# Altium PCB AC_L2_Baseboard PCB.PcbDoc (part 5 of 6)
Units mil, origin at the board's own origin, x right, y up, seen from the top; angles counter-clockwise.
Board outline 7290 x 7055 mil, 4 copper layers (Top Layer, Layer 1, Layer 2, Bottom Layer), stack 70.356 mil thick; 510 components, 285 nets, 1364 pads, 522 vias.
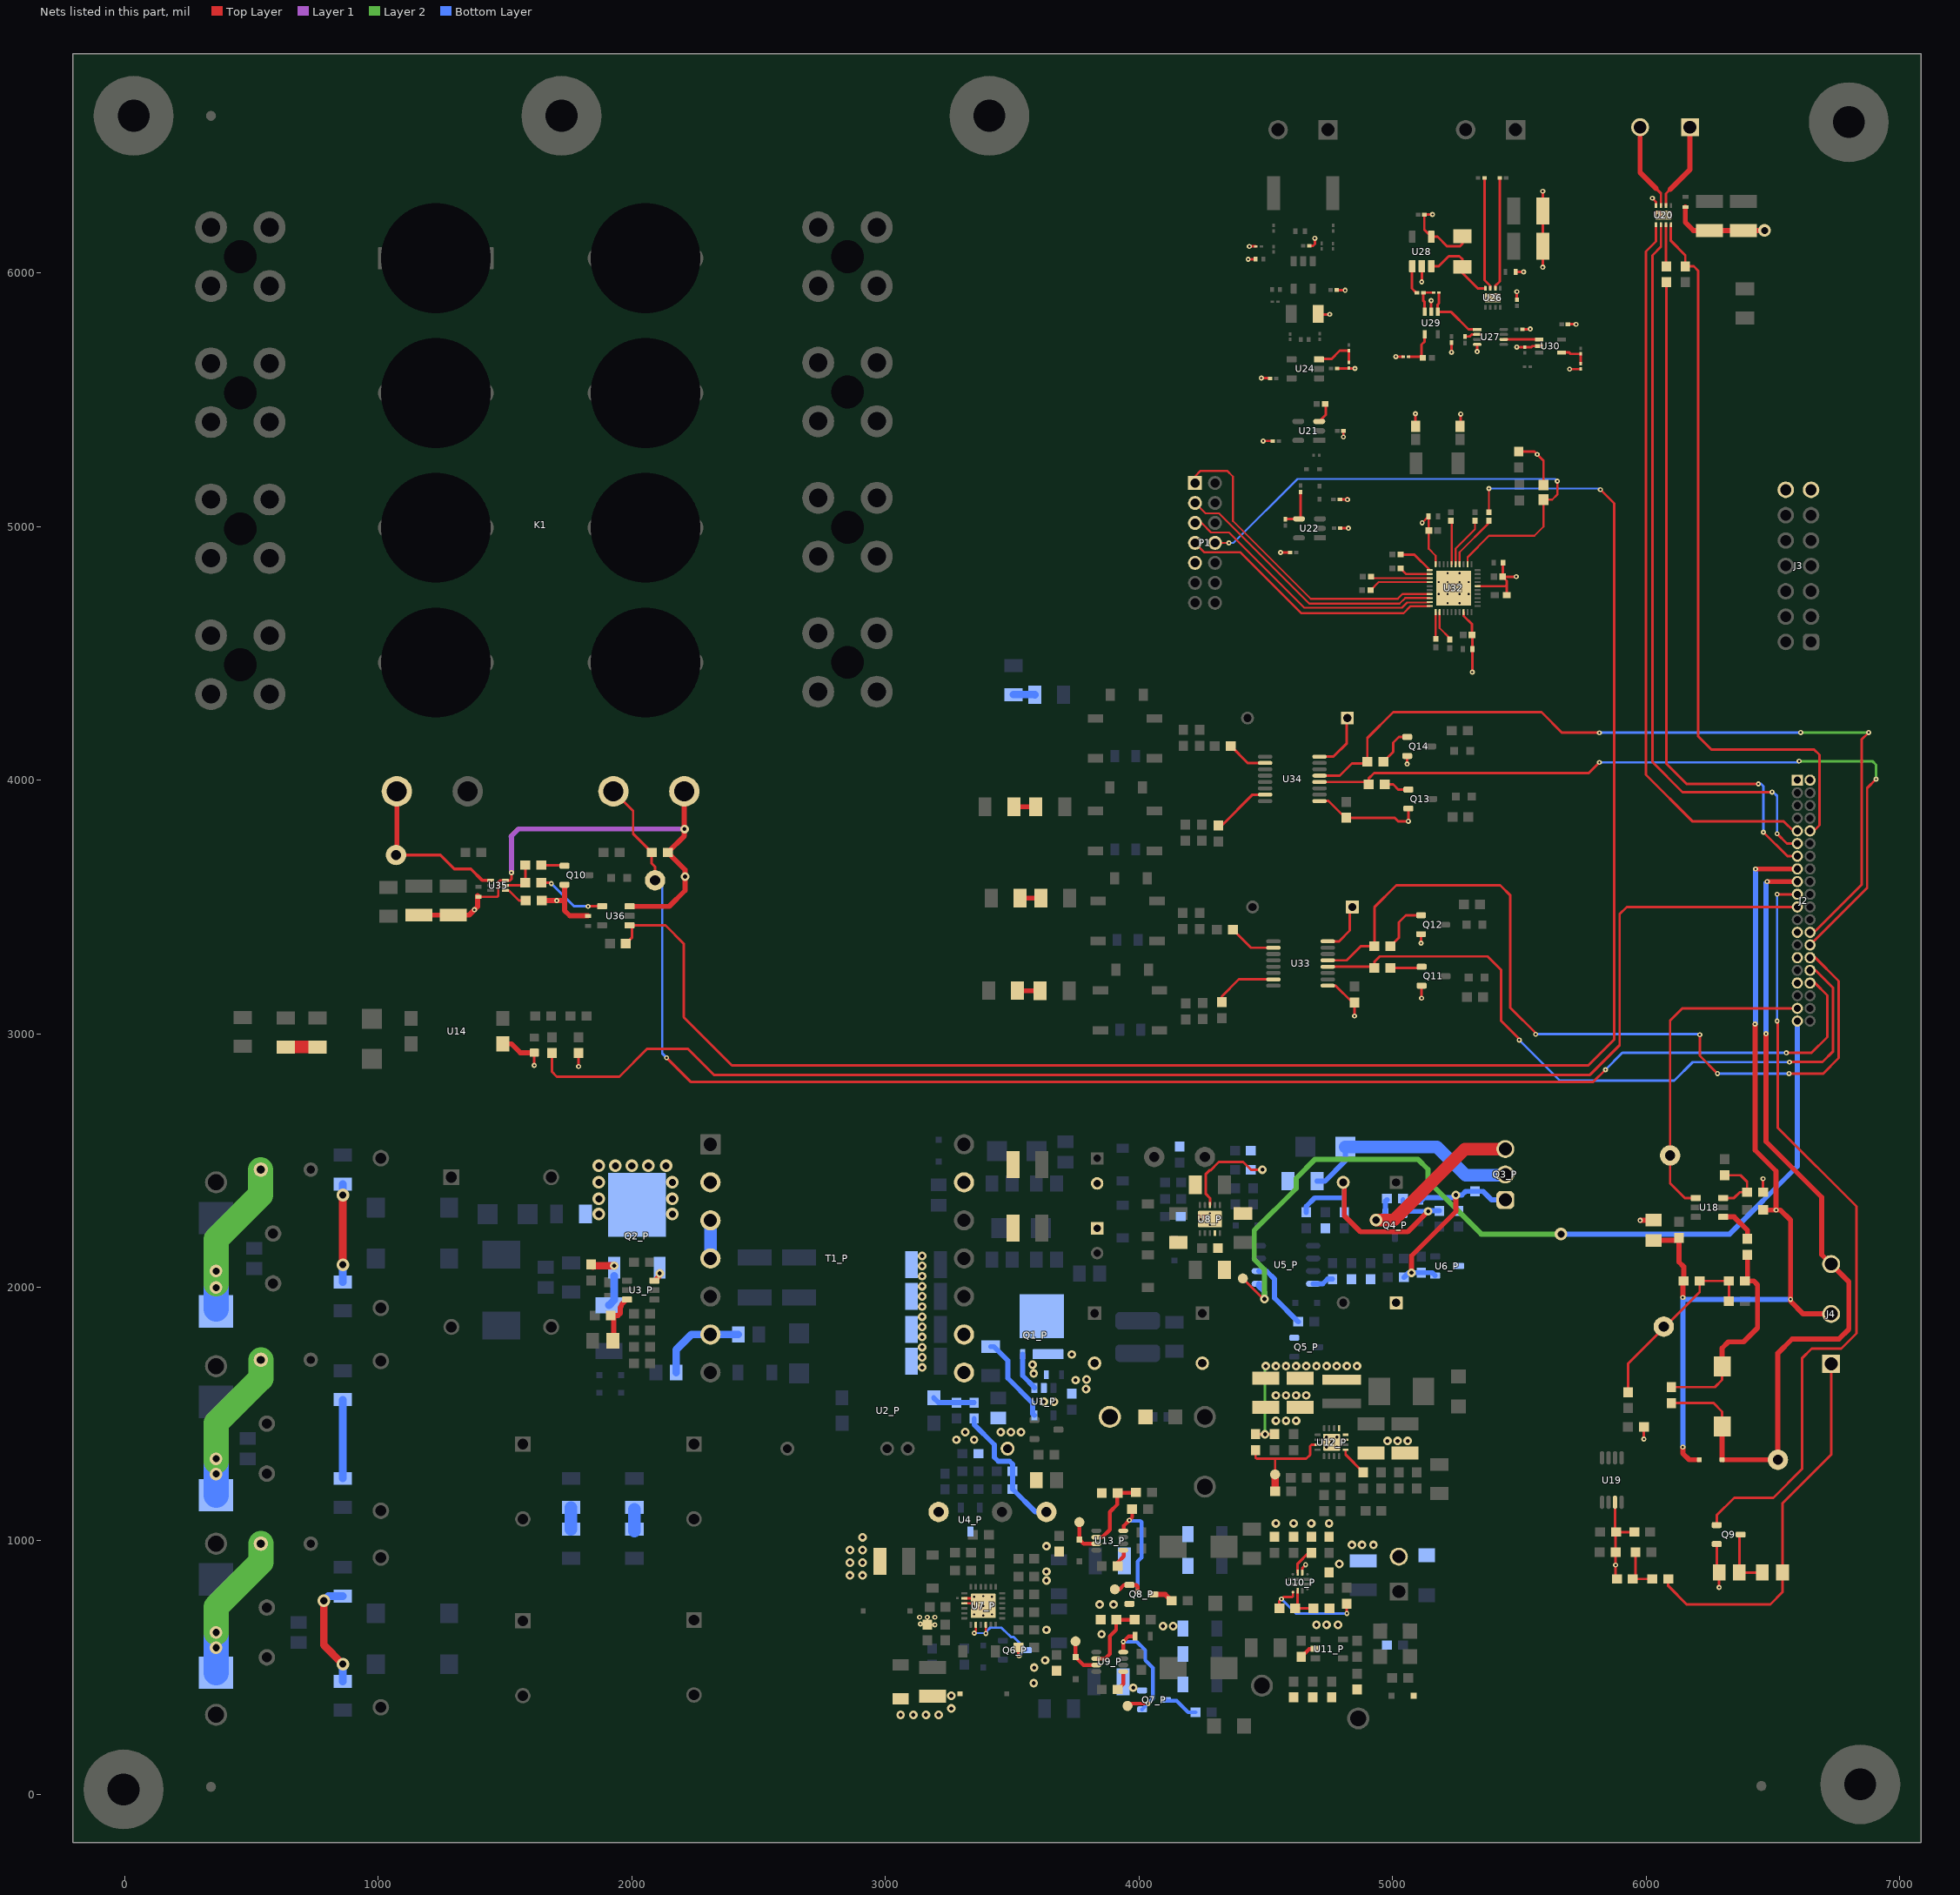
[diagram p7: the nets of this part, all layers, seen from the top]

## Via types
v1: diameter 34, hole 16, Top Layer to Bottom Layer, tented both sides, 231 vias
v2: diameter 20, hole 8, Top Layer to Bottom Layer, tented both sides, 209 vias
v3: diameter 50, hole 28, Top Layer to Bottom Layer, tented both sides, 48 vias
v4: diameter 19.68, hole 7.87, Top Layer to Bottom Layer, 29 vias
v5: diameter 24, hole 12, Top Layer to Bottom Layer, 5 vias

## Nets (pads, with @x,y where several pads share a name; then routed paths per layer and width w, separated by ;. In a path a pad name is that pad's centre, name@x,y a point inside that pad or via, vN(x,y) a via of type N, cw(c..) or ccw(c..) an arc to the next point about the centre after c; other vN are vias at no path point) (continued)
NetD200_P_2: D200_P.2 TP13_P.1 U9_P.7 | length 148.4
  Top Layer w15: TP13_P.1@3750,604 D200_P.2@3750,541.61 3781.35,510.26 U9_P.7@3823,510.26
NetD201_P_2: D201_P.2 TP17_P.1 U13_P.7 | length 142.2
  Top Layer w15: TP17_P.1@3765,1074 D201_P.2@3765,1005.61 3781.81,988.8 U13_P.7@3831.85,988.8
NetF1_P_1: F1_P.1 RT1_P.1 | length 674.1
  Layer 2 w30: RT1_P.1@535,2464 RT1_P.1@536.57,2464
  Layer 2 w100: v3@360,2014 360,2189 535,2364 RT1_P.1@535,2464
  Bottom Layer w100: F1_P.1@360,1914 v3(360,2064)
  other v3: 360,1999
NetF2_P_1: F2_P.1 RT2_P.1 | length 632.2
  Layer 2 w100: v3@360,1314 360,1464 536.57,1640.57 RT2_P.1@536.57,1714
  Bottom Layer w100: F2_P.1@360,1179.94 v3@360,1339
  other v3: 360,1264 360,1324
NetF3_P_1: F3_P.1 RT3_P.1 | length 582.2
  Layer 2 w100: v3(360,639) 360,739 536.57,915.57 RT3_P.1@536.57,989
  Bottom Layer w100: F3_P.1@360,479.94 v3(360,639)
  other v3: 360,579
NetL18_1: L18.1 R85.1 R87.2 R89.2 | length 824.7
  Top Layer w10: R85.1@6100,1606.5 6271.5,1606.5 6300,1635 L18.1@6300,1688.11
  Top Layer w20: L18.1@6300,1688.11 6300,1760 6325,1785 6385,1785 6440,1840 6440,2010 6425,2025 R89.2@6389.84,2025 ; R89.2@6400,2040.16 R87.2@6400,2128.5
NetQ1_P_4: Q1_P.4 U1_P.1 | length 152.5
  Bottom Layer w20: Q1_P.4@3541.54,1736.2 3541.54,1651.56 3588.07,1605.03 3587.6,1604.55 U1_P.1@3587.6,1603.13
NetQ1_P_5-6-7-8: Q1_P.5-6-7-8 R22_P.2 T1_P.8 T1_P.9 U1_P.5 | length 350.5
  Bottom Layer w20: R22_P.2@3415,1766.09 3427.91,1766.09 3482.72,1711.28 3482.72,1641.28 3580.2,1543.8 3580.2,1501.85 3587.18,1494.87 U1_P.5@3587.6,1494.87
NetQ2_P_1: Q2_P.1 U3_P.3 | length 38
  Top Layer w20: U3_P.3@2089.13,2026.4 2090.35,2026.4 2110,2046.05 v1(2110,2055)
NetQ2_P_3: Q2_P.3 R33_P.2 R35_P.2 | length 217.2
  Top Layer w30: R33_P.2@1840,2090.5 1846.5,2084 1847.5,2085 v1(1930,2085)
  Bottom Layer w30: R35_P.2@1910,1929.55 1930,1949.55 Q2_P.3@1930,2045.38
NetQ2_P_4: Q2_P.4 R11_P.1 T1_P.2
  other v3: 1870,2289 2160,2289 1870,2349 2160,2349 1870,2414 2160,2414 1870,2479 1935,2479 2000,2479 2065,2479 2135,2479
NetQ6_P_3: Q6_P.3 R53_P.1 U7_P.8 U7_P.10 | length 424.2
  Top Layer w8: v2(3350.25,636) 3350.25,639.25 3356.25,645.25 3356.25,668.98 U7_P.8@3356.47,669.2 ; U7_P.10@3395.84,669.2 3395.84,635.16 v2(3396,635)
  Top Layer w10: R53_P.1@3511,565.5 R53_P.1@3524.5,579 3524.5,548.5 v2(3527,546)
  Bottom Layer w8: v2(3350.25,636) 3395,636 v2(3396,635)
  Bottom Layer w10: v2(3396,635) 3400.13,635 3400.13,644.47 3413.53,657.87 3457.56,657.87 3484.35,631.09 3485.31,631.09 3495.46,620.94 3506.3,620.94 Q6_P.3@3558.24,569 3550,569 v2(3527,546)
NetQ7_P_1: Q7_P.1 R61_P.1 TP15_P.1 U9_P.4 | length 543.2
  Top Layer w15: U9_P.4@3938.15,561.44 v2(3938.15,602.15) 3960,624 R61_P.1@3983.5,624 ; TP15_P.1@3955,349 3964.29,358.29 v2(4035.39,358.29)
  Bottom Layer w15: v2(3938.15,602.15) 3991.85,602.15 4025,569 4025,529 4055,499 4055,377.9 v2(4035.39,358.29) Q7_P.1@4012.76,335.65
NetQ7_P_3: Q7_P.3 R64_P.1 | length 138.5
  Bottom Layer w15: Q7_P.3@4107.24,373.06 4107.24,369.74 4107.64,369.35 4148.63,369.35 4193.98,324 R64_P.1@4223.5,324
NetQ8_P_1: Q8_P.1 R74_P.1 TP20_P.1 U13_P.4 | length 553.6
  Top Layer w15: TP20_P.1@3905,809 3924,809 3941.4,826.4 Q8_P.1@3962.76,826.4 3989.95,826.4 3995,821.35 v2(3995,799) ; U13_P.4@3938.15,1039.98 3940.51,1042.35 3940.51,1059.96 v2(3962.01,1081.46) 3973.5,1092.96 R74_P.1@3973.5,1125
  Bottom Layer w15: v2(3962.01,1081.46) 3964.47,1079 4005,1079 4010,1074 4010,934 3995,919 v2(3995,799)
NetQ8_P_3: Q8_P.3 R79_P.1 | length 81.6
  Top Layer w20: Q8_P.3@4057.24,789 4103.5,789 R79_P.1@4128.5,764
NetQ9_3: Q9.3 R93.1 R97.2 | length 242.1
  Top Layer w10: Q9.3@6373.29,1025 6368.29,1020 R97.2@6368.29,875 R93.1@6458.29,875
NetQ10_1: Q10.1 R216.2 | length 92.3
  Top Layer w10: R216.2@1642.97,3665.04 1731.63,3665.04 Q10.1@1734.23,3662.44
NetQ11_1: Q11.1 R219.2 | length 125.2
  Top Layer w10: R219.2@4991.5,3260 5110.65,3260 Q11.1@5114.92,3264.27
NetQ12_1: Q12.1 R220.2 | length 208
  Top Layer w10: R220.2@4991.5,3345 5025,3378.5 5025,3440 5052.4,3467.4 Q12.1@5112.76,3467.4
NetQ13_1: Q13.1 R221.2 | length 101.8
  Top Layer w10: R221.2@4968.94,3983.01 5002.44,3983.01 5022.44,3963.01 Q13.1@5062.44,3963.01
NetQ14_1: Q14.1 R222.2 | length 155.7
  Top Layer w10: R222.2@4963.94,4073.01 5002.44,4111.52 5002.44,4148.01 5024.84,4170.41 Q14.1@5057.95,4170.41
NetR2_P_1: R2_P.1 R7_P.2 | length 385.8
  Top Layer w30: v3(860,2089) v3(860,2364)
  Bottom Layer w30: R7_P.2@860,2021.09 v3(860,2089) ; v3(860,2364) R2_P.1@860,2406.91
NetR5_P_1: R5_P.1 R8_P.2 | length 85.8
  Bottom Layer w50: R8_P.2@1760,1046.09 R5_P.1@1760,1131.91
NetR9_P_1: R9_P.1 R12_P.2 | length 310.8
  Bottom Layer w30: R12_P.2@860,1246.09 R9_P.1@860,1556.91
NetR13_P_1: R13_P.1 R17_P.2 | length 85.8
  Bottom Layer w50: R13_P.1@2010,1039 R17_P.2@2010,1124.83
NetR16_P_1: R16_P.1 R19_P.2 | length 431.4
  Top Layer w30: v3(785,764) 785,589 v3(860,514)
  Bottom Layer w30: v3(785,764) 802.91,781.91 R16_P.1@860,781.91 ; R19_P.2@860,446.09 v3(860,514)
NetR21_P_1: R21_P.1 R25_P.2 R27_P.2 TP8_P.1 | length 538.4
  Bottom Layer w20: R25_P.2@3350,1482.5 3350,1459 3430,1379 3430,1329 3445,1314 3490,1314 3501.5,1302.5 R27_P.2@3501.5,1274 R21_P.1@3501.5,1204 3591.5,1114 TP8_P.1@3635,1114
NetR23_P_2: R23_P.2 R26_P.2 T1_P.6 | length 359.9
  Bottom Layer w30: R26_P.2@2175,1664 2175,1754 2235,1814 T1_P.6@2310,1814 R23_P.2@2420,1814
NetR24_P_1: R24_P.1 R25_P.1 U2_P.1 | length 167.1
  Bottom Layer w20: U2_P.1@3190.61,1564 3209.11,1545.5 R24_P.1@3280,1545.5 R25_P.1@3350,1545.5
NetR28_P_1: R28_P.1 R31_P.2 U3_P.6 | length 216.5
  Top Layer w20: R28_P.1@1925,1789 1928.31,1789 1928.31,1877.19 R31_P.2@1916.5,1889 1946.02,1889 1953.82,1896.8 1953.82,1920.51 1958.7,1925.39 1958.7,1931.75 1979.02,1952.07 1979.5,1951.6 U3_P.6@1980.87,1951.6
NetR29_1: R29.1 R83.2 | length 125
  Top Layer w50: R29.1@635,2947.91 R83.2@760,2947.91
NetR36_P_2: R36_P.2 U5_P.6 | length 282.4
  Bottom Layer w20: U5_P.6@4472.72,2064 4503.31,2064 4535,2032.31 4535,1957.5 R36_P.2@4628.5,1864
NetR55_P_1: R55_P.1 U8_P.8 | length 429.9
  Top Layer w10: U8_P.8@4280,2324.12 4280,2352 4264,2368 4264,2447 4278.13,2461.13 4281.9,2461.13 4314.78,2494 4411.5,2494 4441.5,2464 v1(4487,2464)
  Bottom Layer w10: R55_P.1@4441.5,2464 v1(4487,2464)
NetR60_P_1: R60_P.1 R63_P.2 U10_P.1 | length 426.8
  Top Layer w10: R63_P.2@4553.5,734 4553.5,762.5 v2(4561.75,770.75) 4570,779 4605,779 4607.44,781.44 U10_P.1@4607.44,797.66 ; v2(4820,714) R60_P.1@4820,752.5
  Bottom Layer w10: v2(4561.75,770.75) 4618.5,714 v2(4820,714)
NetR62_P_1: R62_P.1 R65_P.2 U9_P.6 | length 278.7
  Top Layer w15: U9_P.6@3831.85,535.85 3866.85,535.85 3885,554 3885,624 3910,649 3910,687.5 R65_P.2@3911.5,689 R62_P.1@3983.5,689
NetR63_P_1: R63_P.1 R67_P.2 U10_P.2 | length 145.6
  Top Layer w10: U10_P.2@4626.14,803.57 4625.63,803.06 4625.63,790.13 4625.31,789.81 4625.31,742.82 R63_P.1@4616.5,734 R67_P.2@4688.5,734
NetR66_P_2: R66_P.2 U10_P.9 | length 107.1
  Top Layer w10: U10_P.9@4626.14,874.43 4626.14,910.14 4668.5,952.5 R66_P.2@4680,952.5
NetR70_P_1: R70_P.1 R201_P.2 TP18_P.1 U12_P.3 | length 449.2
  Top Layer w10: R70_P.1@4460,1357.5 4460,1327.98 4463.98,1324 4535,1324 ; TP18_P.1@4537.01,1262.01 4537.01,1321.99 4535,1324 ; U12_P.3@4704.88,1379.16 4680.16,1379.16 4675,1374 4675,1339 4660,1324 4535,1324
  Top Layer w30: R201_P.2@4537.01,1195 TP18_P.1@4537.01,1262.01
NetR76_P_1: R76_P.1 R80_P.2 U13_P.6 | length 296.5
  Top Layer w15: U13_P.6@3831.85,1014.39 3855.39,1014.39 3885,1044 3885,1114 3915,1144 3915,1187.5 R80_P.2@3916.5,1189 3986.1,1189 R76_P.1@3988.5,1191.4
NetR78_P_2: R78_P.2 U12_P.9 | length 117.9
  Top Layer w10: U12_P.9@4815.12,1359.47 4815.12,1340.38 R78_P.2@4885,1270.5
NetR86_1: R86.1 R88.2 U18.3 | length 244.3
  Top Layer w10: U18.3@6304.13,2352.4 6347.4,2352.4 6370,2375 R88.2@6398.5,2375 6398.5,2416.5 6372.99,2442.01 R86.1@6310,2442.01
NetR87_1: R87.1 U18.1 | length 151.2
  Top Layer w20: U18.1@6304.13,2277.6 6347.4,2277.6 6400,2225 R87.1@6400,2191.5
NetR94_1: R94.1 R95.1 R96.2 | length 186.4
  Top Layer w10: R95.1@5958.5,955 5958.5,860.71 R96.2@5947.8,850 R94.1@6024.8,850
NetR99_2: R99.2 U32.34 | length 219.3
  Top Layer w8: U32.34@5264.65,4851.89 5264.65,4899.06 5380.56,5014.96 R99.2@5380.56,5023.23
NetR125_1: R125.1 U20.7 | length 165.1
  Top Layer w10: U20.7@6078.5,6190.94 6078.5,6027.99 R125.1@6080,6026.5
NetR137_2: R137.2 R138.1 U22.4 | length 164
  Top Layer w10: R138.1@4576.62,5030.77 R138.1@4578.04,5029.35 4578.55,5029.87 4630.69,5029.87 U22.4@4631.2,5030.38 4637.56,5036.74 R137.2@4637.56,5136.17
NetR144_2: R144.2 U21.3 | length 83.3
  Top Layer w10: U21.3@4710.95,5414.8 4736.46,5440.32 R144.2@4736.46,5487.56
NetR151_1: R151.1 U26.2 | length 442.3
  Top Layer w10: U26.2@5405.56,5939.76 5405.56,5949.25 5422.76,5966.45 R151.1@5422.76,6374.96
NetR152_1: R152.1 U26.3 | length 444.5
  Top Layer w10: R152.1@5363.35,6374.96 5363.35,5971.77 5385.87,5949.25 U26.3@5385.87,5939.76
NetR154_2: R154.2 U27.2 | length 51.1
  Top Layer w10: R154.2@5286.56,5749.76 5303.76,5749.76 5311.48,5757.48 5334.03,5757.48 U27.2@5334.36,5757.8
NetR155_1: R155.1 U28.1 | length 115.1
  Top Layer w10: U28.1@5078.16,6026.89 5076.86,6025.59 5076.86,5939.09 5094.39,5921.56 R155.1@5096.35,5921.56
NetR155_2: R155.2 R156.1 U29.3 | length 114.8
  Top Layer w10: R155.2@5121.95,5921.56 5121.95,5890.34 5126.97,5885.32 U29.3@5126.97,5847.14 ; R155.2@5124.45,5922.96 R156.1@5161.73,5922.96 R156.1@5162.73,5922.96
NetR156_2: R156.2 U27.1 U29.1 | length 263
  Top Layer w10: R156.2@5183.38,5922.96 5183.38,5880.38 5178.15,5875.15 U29.1@5178.15,5847.14 5230.05,5847.14 5299.7,5777.49 U27.1@5334.36,5777.49
NetR175_2: R175.2 U32.1 | length 139.1
  Top Layer w10: R175.2@5032.41,4889.72 5086.15,4889.72 U32.1@5146.54,4829.33
NetR178_2: R178.2 U32.2 | length 123.3
  Top Layer w8: R178.2@5032.41,4834.72 5054.61,4812.52 U32.2@5146.54,4812.52
NetR179_2: R179.2 U32.3 | length 236.6
  Top Layer w8: R179.2@4911.73,4801 4915.96,4796.77 U32.3@5146.54,4796.77
NetR180_2: R180.2 U32.4 | length 246.1
  Top Layer w8: R180.2@4913.73,4749 4945.76,4781.02 U32.4@5146.54,4781.02
NetR184_2: R184.2 U32.11 | length 105.9
  Top Layer w8: U32.11@5170.16,4662.91 5170.16,4558.27 R184.2@5171.03,4557.4
NetR187_2: R187.2 U32.12 | length 125.4
  Top Layer w8: U32.12@5185.91,4662.91 5185.91,4600.31 5226.03,4560.2 R187.2@5226.03,4554.13
NetR189_2: R189.2 U32.35 | length 203.1
  Top Layer w8: U32.35@5248.9,4851.89 5248.9,4913.31 5325.56,4989.96 R189.2@5325.56,5023.23
NetR190_2: R190.2 U32.36 | length 172.4
  Top Layer w8: R190.2@5230.56,5023.23 5233.16,5020.63 U32.36@5233.16,4851.89
NetR192_2: R192.2 R193.1 | length 89
  Top Layer w20: R193.1@3521.34,3170 3521.77,3169.57 R192.2@3610.16,3169.57
NetR194_1: R194.1 U33.15 | length 254.1
  Top Layer w10: R194.1@4326.73,3124.19 4326.73,3146.73 4394.37,3214.37 U33.15@4530.28,3214.37
NetR195_2: R195.2 R196.1 | length 82
  Top Layer w20: R196.1@3532.01,3534.57 R196.1@3531.57,3535 R195.2@3612.91,3535
NetR198_1: R198.1 U33.10 | length 188.6
  Top Layer w10: R198.1@4370.94,3410 4441.57,3339.37 U33.10@4530.28,3339.37
NetR200_2: R200.2 R201.1 | length 85.9
  Top Layer w20: R201.1@3507.01,3895.31 R200.2@3592.91,3895.31
NetR202_1: R202.1 U34.15 | length 234.4
  Top Layer w10: R202.1@4313.54,3821.5 4326.5,3821.5 4447.81,3942.81 U34.15@4497.72,3942.81
NetR203_2: R203.2 R204.1 | length 84.1
  Bottom Layer w30: R204.1@3505,4337.48 3588.43,4337.48 R203.2@3588.91,4337
NetR206_1: R206.1 U35.1 | length 96.6
  Top Layer w10: U35.1@1501.47,3565.04 1514.96,3565.04 1554.96,3525.04 R206.1@1581.47,3525.04
NetR207_1: R207.1 U34.10 | length 163.6
  Top Layer w10: R207.1@4361.93,4135 4429.11,4067.81 4442.64,4067.81 U34.10@4497.72,4067.81
NetR209_1: R209.1 U36.4 | length 279.1
  Top Layer w10: R209.1@1642.97,3595.04 v2@1684.96,3595.04 ; v2(1827.56,3502.44) U36.4@1882.34,3502.44
  Bottom Layer w10: v2(1682.56,3592.44) 1772.56,3502.44 v2(1827.56,3502.44)
NetT1_P_3: T1_P.3 T1_P.4 | length 150
  Bottom Layer w50: T1_P.4@2310,2114 T1_P.3@2310,2264
NetU27_6: U27.6 U30.1 | length 140.7
  Top Layer w10: U27.6@5438.76,5738.12 5439.04,5737.83 5577.65,5737.83 5577.82,5738 U30.1@5578.27,5737.55 U30.1@5577.72,5737
OUT1: J15.1 U20.2 | length 348.6
  Top Layer w10: U20.2@6078.5,6265.75 6078.5,6313.5 6095,6330
  Top Layer w20: 6095,6330 6173.43,6408.43 J15.1@6173.43,6575
OUT2: J15.2 U20.3 | length 343.3
  Top Layer w10: 6040,6333 6058.82,6314.18 U20.3@6058.82,6265.75
  Top Layer w20: J15.2@5976.57,6575 5976.57,6396.43 6040,6333
PE_CP: C99.2 C100.2 D35.2 J2.15 J4.2 NT3.2 R91.1 | length 3637.8
  Top Layer w10: C99.2@6120,2185 C99.2@6130,2195 ; R91.1@6145,2021.5 R91.1@6148.5,2025 ; v2@6570,1945 v2(6570,1952.5)
  Top Layer w20: NT3.2@6030,2185 C99.2@6120,2185 ; C99.2@6130,2195 6130,2100 6148.5,2081.5 R91.1@6148.5,2025 ; v2(6145,1370) 6145,1345 6170,1320 D35.2@6210.12,1320 ; v2(6145,1960) R91.1@6145,2021.5 ; v2(6430,3038) 6430,2541 6513,2458 v2(6513,2305) ; v2(6432,3650) J2.15@6597,3650 ; C100.2@6461.5,2305 v2(6513,2305) ; v2@6570,1945 6620,1895 J4.2@6730,1895 ; v2(6570,1952.5) 6570,2265 6530,2305 v2(6513,2305)
  Bottom Layer w10: v2(6145,1960) 6152.5,1952.5 ; v2(6430,3038) v2@6432,3040
  Bottom Layer w20: v2(6145,1370) v2(6145,1960) ; 6152.5,1952.5 v2(6570,1952.5) ; v2@6432,3040 v2(6432,3650)
PGND: C3_P.1 C4_P.2 C5_P.2 C10_P.1 C12_P.1 C18_P.2 C19_P.2 C21_P.2 C22_P.2 C23_P.2 C24_P.2 C25_P.2 C26_P.2 C27_P.2 C31_P.2 C33_P.2 C39_P.1 C40_P.2 C41_P.2 C42_P.2 C43_P.2 C44_P.2 C47_P.2 C48_P.2 C50_P.2 C51_P.2 C53_P.2 C54_P.2 C59_P.2 C60_P.1 C61_P.2 C64_P.2 C65_P.2 C66_P.2 C67_P.2 C68_P.2 C69_P.2 C70_P.2 C71_P.1 C72_P.2 C73_P.2 C74_P.2 C75_P.1 C76_P.2 C77_P.2 C79_P.2 C80_P.2 C81_P.2 C83_P.2 C84_P.2 C87_P.2 C88_P.2 C89_P.2 C90_P.2 C94_P.1 C96.2 C98.1 C108.2 C109.2 C110.2 C111.2 C114.2 C115.2 C116.2 C117.1 C118.1 C119.1 C120.1 C121.1 C122.1 C123.1 C124.1 C125.1 C126.1 C127.1 C128.1 C133.2 C134.2 C138.2 C139.2 C140.2 C141.2 C146.2 C147.1 C148.1 C149.2 C150.1 C151.2 C152.2 C153.1 C154.2 C155.1 C157.2 C159.1 C160.2 C161.2 C162.2 C164.2 C166.1 C167.2 C800.1 D11_P.1 D26_P.2 D28_P.1 J1_P.2 J2.1 J2.2 J2.25 J2.29 J2.33 J3.13 J3.14 K1.8 L10_P.2 NT1_P.1 NT2_P.2 NT3.1 P1.9 Q1_P.1-2-3 Q5_P.2 Q7_P.2 Q8_P.2 Q9.2 Q10.2 Q11.2 Q12.2 Q13.2 Q14.2 R32_P.1 R44_P.1 R45_P.1 R49_P.1 R65_P.1 R66_P.1 R67_P.1 R68_P.1 R80_P.1 R88.1 R96.1 R97.1 R131.1 R133.1 R134.1 R147.1 R148.2 R153.1 R188.1 R202_P.1 R206.2 R218.2 T1_P.13 TP7_P.1 TP9_P.1 U1_P.2 U4_P.3 U5_P.4 U6_P.3 U7_P.2 U7_P.3 U7_P.25@3386,744 U8_P.4 U8_P.11 U9_P.1 U10_P.8 U11_P.2 U12_P.11 U12_P.12 U12_P.13 U12_P.17@4760,1389 U13_P.1 U14.3 U19.3 U20.4 U20.9 U26.9 U27.4 U28.2 U28.4 U29.2 U30.2 U32.18 U32.26 U32.40 U32.41 U33.1 U33.8 U34.1 U34.8 U35.3 U36.3 | length 7916.2
  Top Layer w8: v2(4490,5337.4) C123.1@4527.61,5337.4 ; C166.1@4820,4243.15 C166.1@4821.85,4245 ; v2(5116.86,5014.96) C154.2@5141.86,5039.96 5143.23,5038.58 C155.1@5143.23,4984.96 5143.23,4912.28 5170.16,4885.35 U32.40@5170.16,4851.89 ; U32.26@5335.52,4765.28 5445.2,4765.28 5451.03,4771.1
  Top Layer w10: C162.2@1395,3540 1469,3540 1473,3544 1473,3598 1479.41,3604.41 U35.3@1501.47,3604.41 1519.41,3604.41 1525,3610 v2(1525,3635) ; v2(1615,2875) C98.1@1615,2925.47 ; v2(1790,2871) C96.2@1790,2923.5 ; U7_P.3@3311.2,753.84 3337.77,753.84 v4(3347.61,744) ; U7_P.2@3311.2,773.53 3354.47,773.53 3350,778 v4(3350,780) ; v2(4430.56,6053.96) 4431.1,6054.5 4458.9,6054.5 C134.2@4459.44,6055.04 ; v2(4435.56,6104.96) R148.2@4460.91,6105 ; v2(4482.56,5585.96) 4483.34,5585.18 4516.83,5585.18 C122.1@4517.61,5584.4 ; v2(4558.56,4897.96) C124.1@4596.73,4897.96 ; 4644.02,887.12 4644.02,893.02 v2(4657,906) ; C117.1@4671.79,6106.96 4686.63,6106.96 4694,6114.33 v2@4694,6136.52 ; C133.2@4706.41,5826.07 C133.2@4706.41,5838.79 4708.24,5836.96 v2(4752.56,5836.96) ; U34.1@4712.28,3917.81 4747.64,3917.81 4813.94,3851.52 C164.2@4817.44,3851.52 5008.94,3851.52 5022.44,3838.01 v2(5062.44,3838.01) Q13.2@5062.44,3888.21 ; U34.8@4712.28,4092.81 4767.24,4092.81 4820,4145.57 C166.1@4820,4243.15 ; U33.1@4744.84,3189.37 4775.63,3189.37 4841.5,3123.5 C157.2@4850,3123.5 ; U33.8@4744.84,3364.37 4789.37,3364.37 4831.85,3406.85 4831.85,3490 C159.1@4841.85,3500 ; C121.1@4780.17,5933.04 4780,5933.04 4780.54,5932.5 4813.02,5932.5 v2(4813.56,5931.96) ; C118.1@4781.55,5623.4 v2@4854.6,5623.4 ; R147.1@4792.56,5106.96 v2@4821.95,5106.96 ; C120.1@4793.78,4993.57 v2(4826.34,4993.57) ; v2(4806.57,5353.43) C119.1@4806.57,5377.4 ; R131.1@4826.53,5624.07 R131.1@4827.59,5625.13 ; v2(4850,3070) 4850,3103.5 ; v2(5013.26,5670.26) R133.1@5041.73,5670.26 ; v2(5057.95,4063.52) Q14.2@5057.95,4095.61 ; v2(5090.14,5444.99) 5090.14,5395.59 C147.1@5090.56,5395.18 ; v2(5112.76,3357.24) Q12.2@5112.76,3392.6 ; v2@5114.92,3135.08 v2(5114.92,3140) Q11.2@5114.92,3189.47 ; v2(5115.56,5964.96) U28.2@5115.56,6026.89 ; U29.2@5152.56,5847.14 v2(5152.56,5890.96) ; v2(5157.89,6230.66) 5157.54,6230.31 5125.9,6230.31 C127.1@5125.56,6229.96 5125.56,6170.43 U28.4@5152.96,6143.03 5177.49,6143.03 5215.56,6104.96 5265.56,6104.96 5275.56,6114.96 R153.1@5275.56,6145.04 ; v2@5232.96,5682.44 C125.1@5232.96,5725.46 ; C148.1@5265.56,5395.18 5269.14,5398.77 v2(5269.14,5443.99) ; U32.18@5280.4,4662.91 5281.21,4662.1 5281.21,4647.7 5313.35,4615.56 C150.1@5313.35,4572.4 5314.73,4571.02 C149.2@5314.73,4517.4 v2(5314.73,4425.79) ; v2@5334.36,5690.16 U27.4@5334.36,5718.43 ; C152.2@5436.11,4857.4 5434.73,4856.02 C153.1@5434.73,4802.4 ; C146.2@5451.03,4729.72 5451.03,4771.1 5451.03,4786.1 C153.1@5434.73,4802.4 ; v2(5488,4802.4) C153.1@5434.73,4802.4 ; C140.2@5489.57,6004.34 v2@5519.57,6004.34 ; v2(5490.43,5707.96) C141.2@5521.54,5707.97 ; v2(5490.56,5926.59) 5490.8,5926.36 5490.8,5894.78 C126.1@5491.04,5894.54 ; C151.2@5497.82,5295.91 5559.61,5295.91 v2(5570.56,5284.96) 5595.56,5259.96 R188.1@5595.56,5163.53 ; C800.1@5511.98,5778 5511.81,5778 5512.4,5778.59 5542.71,5778.59 v2(5543.3,5779.17) ; C141.2@5521.56,5707.98 5547.71,5707.98 5551.69,5711.96 U30.2@5578.27,5711.96 ; v2@5592.64,6032.05 C138.2@5592.64,6104.96 C139.2@5592.64,6244.96 v2(5592.64,6322.87) ; C128.1@5691.54,5797.96 v2(5723.96,5797.96) ; v2(5698.38,5621.13) R134.1@5742.56,5621.13 ; U19.3@5877.8,1152.4 5877.8,1035.71 C109.2@5878.5,1035 ; R96.1@5884.8,850 5880,854.8 C108.2@5880,955 5880,1033.5 C109.2@5878.5,1035 ; C111.2@5953.5,1035 C109.2@5881.5,1035 C109.2@5878.5,1035 ; v2(5991.5,1401.5) C110.2@5991.5,1450 ; v2(6025,6295) 6039.13,6280.87 U20.4@6039.13,6265.75 ; NT3.1@6029,2264 NT3.1@6030,2265 ; Q9.2@6278.8,987.6 6278.8,884.49 R97.1@6288.29,875 v2(6288.29,816.71) ; v2@6460,2430 v2(6461.5,2428.5) R88.1@6461.5,2375
  Top Layer w15: C65_P.2@3916.5,414 3938.15,435.65 U9_P.1@3938.15,484.67 ; C88_P.2@3916.5,900.61 3916.5,915.5 3940,939 3940,961.36 U13_P.1@3938.15,963.21 ; C81_P.2@4640,542.5 4671.5,574 U11_P.2@4698.82,574
  Top Layer w20: C160.2@1160,3467.91 C161.2@1295,3467.91 1357.99,3467.91 v2(1379,3488.92) 1391.47,3501.4 C162.2@1391.47,3545.04 ; U14.3@1490.61,2960 1525,2960 1559.53,2925.47 C98.1@1615,2925.47 ; R206.2@1644.47,3525.04 1729.19,3525.04 1734.23,3520 ; Q10.2@1734.23,3587.64 1734.23,3520 ; C167.2@1826.47,3465.04 1754.96,3465.04 1734.23,3485.77 1734.23,3520 ; U36.3@1990.61,3502.44 2147.44,3502.44 2210,3565 v1(2210,3620) 2210,3646.51 R218.2@2141.47,3715.04 2206.93,3780.49 K1.8@2206.93,3955.94 ; v2@4821.95,5106.96 v2(4822.34,5106.57) ; v2(5977,2264) NT3.1@6029,2264 ; C116.2@6155,6260 6155,6200 6187.2,6167.8 C115.2@6249.76,6167.8 C114.2@6384.33,6167.8 v3(6467.8,6167.8)
  Layer 1 w20: v2@1525,3634.92 v2(1525,3635) 1525,3775.12 1522.56,3777.56 1552.44,3807.44 v1(2207.56,3807.44)
  Bottom Layer w20: U5_P.4@4687.28,2014 4725,2014 4743.5,2032.5 C42_P.2@4763.7,2032.5
  other v1: 3060,314 3110,314 3160,314 3210,314 3260,339 3260,389 3977.52,421.01 3585,439 3586.79,500.1 3630,529 3852.65,632.15 3635,649 4095,664 4135,664 4700,669 4740,669 4785,669 3845,749 3900,749 3635,844 2860,864 2910,864 3635,879 4790,909 2860,914 2910,914 2860,964 2910,964 3635,979 4840,984 4880,984 4925,984 2910,1014 4540,1069 4610,1069 4680,1069 4750,1069 4980,1394 5020,1394 5060,1394 3280,1399 3350,1399 3315,1429 3455,1429 3495,1429 3535,1429 4540,1474 4580,1474 4620,1474 3625,1549 3665,1549 4540,1574 4580,1574 4620,1574 4660,1574 3791.02,1599 3750,1634 3793.43,1636.53 3585,1660 3145,1684 3580,1695 3145,1724 3735,1735 3145,1764 3145,1804 3145,1844 3145,1884 3145,1924 3145,1964 3145,2004 3145,2044 3145,2084 3145,2124
  other v2: 3195,669 3138.25,672.25 3135,699 3165,699 3195,699 5880,904.9 1704,3525.04 4851.86,5623.4 5232.96,5687.44 5334.24,5690.02 5517.13,6004.34 5592.64,6022.87 4693.56,6136.96
  other v4: 3386,705.61 3350,710 3420,710 3386,744 3424.39,744 3420,780 3386,782.39 4280,2246.36 4242.6,2269 4317.4,2269 4280,2291.64 5217.41,4698.35 5264.65,4698.35 5181.97,4733.78 5217.41,4733.78 5264.65,4733.78 5300.08,4733.78 5181.97,4781.02 5217.41,4781.02 5264.65,4781.02 5300.08,4781.02 5217.41,4816.46 5264.65,4816.46 5374.06,5902.36 5417.37,5902.36 6047.01,6228.35 6090.31,6228.35
  other v5: 4740,1369 4780,1369 4760,1389 4740,1409 4780,1409
PILOT_ADC: R89.1 R90.1 R91.2 R92.1 TP26.1 | length 750.5
  Top Layer w10: R92.1@5930,1586.5 5930,1700 6090,1860 6211.5,1981.5 R91.2@6211.5,2025 R89.1@6326.85,2025 R90.1@6326.85,1945
PILOT_OUT: D35.1 J2.17 J4.3 L18.2 R85.2 TP24.1 | length 3379.6
  Top Layer w10: R85.2@6100,1543.5 6266.5,1543.5 6300,1510 L18.2@6300,1451.89
  Top Layer w20: D35.1@6300,1320 TP24.1@6520,1320 6520,1740 6576,1796 6761,1796 6800,1835 6800,2021.85 J4.3@6730,2091.85 6693,2128.85 6693,2355 6473,2575 v2(6473,3000) ; D35.1@6300,1325.12 L18.2@6300,1451.89 ; v2(6478,3600) J2.17@6597,3600
  Bottom Layer w10: v2@6473,3595 v2(6478,3600)
  Bottom Layer w20: v2(6473,3000) v2@6473,3595
PILOT_PWM: J2.37 TP25.1 U18.4 | length 1288.6
  Top Layer w10: U18.4@6195.87,2352.4 6152.6,2352.4 6095,2410 TP25.1@6095,2520 6095,3052 6143,3100 J2.37@6597,3100
PLC_ZC_IN: C97.2 J2.21 | length 5658.7
  Top Layer w10: C97.2@1685,2923.5 1685,2850 1704,2831 1950.5,2831 2060.5,2941 2220,2941 2323,2838 5779,2838 5896,2955 5896,3472 5924,3500 J2.21@6597,3500
PLug_IN1: J2.11 U20.6 | length 2925.6
  Top Layer w10: U20.6@6058.82,6190.94 6058.82,6103.82 6025,6070 6025,4072 6144,3953 v2(6497,3953) ; v2(6517,3789) 6556,3750 J2.11@6597,3750
  Bottom Layer w10: v2(6497,3953) 6502,3953 6517,3938 v2(6517,3789)
PLug_IN2: J2.9 U20.5 | length 2874.7
  Top Layer w10: U20.5@6039.13,6190.94 6039.13,6124.13 6000,6085 6000,4021 6184,3837 6544,3837 6581,3800 J2.9@6597,3800
PLug_MODE: J2.13 R125.2 | length 2672.7
  Top Layer w10: R125.2@6080,5963.5 6080,4065 6160,3985 v2(6443,3985) ; v2(6463,3795) 6558,3700 J2.13@6597,3700
  Bottom Layer w10: v2(6443,3985) 6454,3985 6463,3976 v2(6463,3795)
Plug_nSLEEP: J2.10 R126.2 U20.8 | length 2914.6
  Top Layer w10: U20.8@6098.19,6190.94 6098.19,6126.81 6155,6070 R126.2@6155,6026.5 6188.5,6026.5 6205,6010 6205,4174 6258,4121 6663,4121 6684,4100 6684,3822 6662,3800 J2.10@6647,3800
PP_ADC: J4.1 R93.2 R94.2 | length 1507.5
  Top Layer w10: R94.2@6087.8,850 6087.8,822.2 6160,750 6490,750 6538.29,798.29 R93.2@6538.29,875 6538.29,1148.29 6730,1340 J4.1@6730,1698.15
PP_GPIO: J2.19 Q9.1 | length 3084.3
  Top Layer w10: Q9.1@6278.8,1062.4 6278.8,1100.8 6348,1170 6502,1170 6615,1283 6615,1720 6653,1758 6770,1758 6830,1818 6830,2319 6519,2630 6519,3048 v2(6517,3050) ; v2(6517,3550) J2.19@6597,3550
  Bottom Layer w10: v2(6517,3050) v2(6517,3550)
Q3_P_Drain: C33_P.1 D15_P.1 Q3_P.2 R34_P.1 | length 879.3
  Bottom Layer w20: C33_P.1@4702.09,2419 4734,2419 4813.74,2498.74 D15_P.1@4813.74,2554 ; Q3_P.2@5441.5,2441.5 Q3_P.2@5445,2445
  Bottom Layer w50: D15_P.1@4813.74,2554 5176,2554 5288.5,2441.5 R34_P.1@5325,2441.5 Q3_P.2@5441.5,2441.5
Q3_P_Gate: C36_P.1 D17_P.2 Q3_P.1 R34_P.2 R41_P.1 U6_P.1 | length 879.3
  Top Layer w20: v1(5074.72,2057.5) 5074.72,2123.72 5250,2299 v1(5250,2364)
  Bottom Layer w20: R41_P.1@5045.2,2039 5063.7,2057.5 v1(5074.72,2057.5) C36_P.1@5113.7,2057.5 5156.85,2057.5 U6_P.1@5167.76,2046.6 ; D17_P.2@5110,2338.8 5125.2,2354 5240,2354 v1(5250,2364) 5274,2364 5288.5,2378.5 R34_P.2@5325,2378.5 5357.44,2378.5 5391.34,2344.61 Q3_P.1@5445,2344.61
Q3_P_Source: Q3_P.3 Q4_P.1 R38_P.2 | length 737
  Top Layer w50: v3(4935.14,2265) 5005,2265 5285.39,2545.39 Q3_P.3@5445,2545.39
  Bottom Layer w20: v3@4940,2260.14 v3(4935.14,2265) 4944.86,2265 Q4_P.1@4972.6,2292.74 4972.6,2339.59 R38_P.2@4978.5,2345.5
R_MIRROR_OUT: J2.34 K1.7 R218.1 TP28.1 | length 6097
  Top Layer w10: K1.7@1927.4,3955.94 2005,3878.35 2005,3788.52 R218.1@2078.48,3715.04 2078.48,3671.52 2091.47,3658.53 TP28.1@2091.47,3605.04 ; v2(2137,2905) 2231.5,2810.5 5792.5,2810.5 v2(5840,2858) ; v2(6553.5,2924.5) 6652.5,2924.5 6715,2987 6715,3151 6666,3200 J2.34@6647,3200
  Bottom Layer w10: TP28.1@2091.47,3605.04 2119.96,3605.04 2119.96,2922.04 v2(2137,2905) ; v2(5840,2858) 5906.5,2924.5 v2(6553.5,2924.5)
RCD_FAULT: R99.1 R210.1 U36.1 | length 7128.5
  Top Layer w8: R99.1@5380.56,5055.71 R99.1@5380.56,5056.69 v2(5380.56,5149.96)
  Top Layer w10: R210.1@1976.5,3355 2000,3378.5 2000,3418.25 U36.1@1990.61,3427.64 2132.36,3427.64 2205,3355 2205,3065 2394.5,2875.5 5772.5,2875.5 5874,2977 5874,5092 v2@5826,5140
  Bottom Layer w8: v2(5380.56,5149.96) 5816.04,5149.96 v2(5820,5146)
RELAY_CHECK_L1: J2.32 R219.1 U33.4 | length 2762.1
  Top Layer w10: U33.4@4744.84,3264.37 4924.13,3264.37 R219.1@4928.5,3260 4928.5,3283.5 4950,3305 5375,3305 5429,3251 5429,3050 v2@5502,2977 ; 6576,2889 6696,2889 6738,2931 6738,3181 6669,3250 J2.32@6647,3250
  Bottom Layer w10: v2(5500,2975) 5660,2815 6111,2815 6184,2888 v2(6566,2888) ; J2.32@6647,3250 J2.32@6651,3246
RELAY_CHECK_L2: J2.30 R220.1 U33.5 | length 3327.7
  Top Layer w10: U33.5@4744.84,3289.37 4819.37,3289.37 4875,3345 R220.1@4928.5,3345 4928.5,3498.5 5015,3585 5425,3585 5465,3545 5465,3102 5567,3000 v2@5567,2999 ; v2(6212,2996) 6212,2913 v2(6282,2843) ; v2(6564,2843) 6699,2843 6760,2904 6760,3208 6668,3300 J2.30@6647,3300
  Bottom Layer w10: v2(5565,2998) v2@6212,2998 ; v2@6279,2843 v2(6282,2843) v2(6564,2843)
RELAY_CHECK_L3: J2.28 R221.1 U34.4 | length 3071.2
  Top Layer w10: U34.4@4712.28,3992.81 4902.5,3992.81 R221.1@4905,3995.31 ; R221.1@4905.94,3983.01 4905.94,4006.52 4927.44,4028.01 5774.01,4028.01 v2(5816,4070) ; J2.28@6647,3350 6872,3575 6872,3969 v2(6907,4004)
  Layer 2 w10: v2(6604,4075) 6893,4075 6907,4061 v2(6907,4004)
  Bottom Layer w10: v2(5816,4070) 6599,4070 v2(6604,4075)
RELAY_CHECK_N: J2.26 R222.1 U34.5 | length 3250.5
  Top Layer w10: U34.5@4712.28,4017.81 4792.24,4017.81 4839.74,4065.31 R222.1@4903.5,4065.31 ; R222.1@4900.94,4073.01 4900.94,4166.52 5002.44,4268.01 5587.99,4268.01 5669,4187 v2(5816,4187) ; J2.26@6647,3400 6663,3400 6850,3587 6850,4160 v2(6878,4188)
  Layer 2 w10: v2(6610,4188) v2(6878,4188)
  Bottom Layer w10: v2(5816,4187) 5817,4188 v2(6610,4188)
RELAY_OH: K1.5 TP27.1 U35.4 | length 671.4
  Top Layer w10: 1360,3650 1365,3650
  Top Layer w12: TP27.1@1070,3705 1245,3705 1300,3650 1360,3650 ; 1365,3650 1410.59,3604.41 U35.4@1443.21,3604.41
  Top Layer w20: TP27.1@1070,3705 1073.07,3708.07 K1.5@1073.07,3955.94 K1.5@1070,3952.87
RELAY_STATE: R209.2 R216.1 U35.2 | length 152.8
  Top Layer w10: U35.2@1501.47,3584.72 1569.66,3584.72 R209.2@1579.98,3595.04 R216.1@1579.98,3665.04
Super_Cap_Char: J2.39 TP10_P.1 U5_P.5 | length 3591.1
  Top Layer w10: TP10_P.1@4410,2035 4491,1954 v1(4495,1954)
  Layer 2 w20: v1(4495,1954) 4495,2070 4455,2110 4455,2225 4620,2390 4620,2430 4695,2505 5100,2505 5140,2465 5140,2420 5350,2210 v3(5665,2210)
  Bottom Layer w20: U5_P.5@4472.72,2014 4472.72,2009.14 4470.09,2006.52 4495,1981.61 v1(4495,1954) ; v3(5665,2210) 6330,2210 6597,2477 J2.39@6597,3050
TCK: P1.7 U32.10 | length 1052.2
  Top Layer w8: P1.7@4221.26,4935.78 4258.82,4898.22 4400.78,4898.22 4641,4658 5043,4658 5071.54,4686.54 U32.10@5146.54,4686.54
TDI: P1.3 U32.8 | length 1099
  Top Layer w8: P1.3@4221.26,5093.26 4262.44,5052.08 4315.56,5052.08 4671.64,4696 5028,4696 5050.03,4718.03 U32.8@5146.54,4718.03
TDO: P1.1 U32.7 | length 1280
  Top Layer w8: P1.1@4221.26,5172 4221.26,5198.26 4243,5220 4348,5220 4371,5197 4371,5022 4678.04,4714.96 5020.56,4714.96 5039.38,4733.78 U32.7@5146.54,4733.78
TEST: P1.8 R188.2 U32.32 | length 2052.6
  Top Layer w8: P1.8@4300,4935.78 v2(4354.78,4935.78) ; U32.32@5296.15,4851.89 5296.15,4879.37 5380.56,4963.78 5559.38,4963.78 5595.56,4999.96 R188.2@5595.56,5106.39 5630.1,5106.39 5650,5126.29 v2(5650,5179)
  Bottom Layer w8: v2(4354.78,4935.78) 4372.78,4935.78 4625,5188 5641,5188 v2@5647,5182
TMS: P1.5 U32.9 | length 1073.1
  Top Layer w8: P1.5@4221.26,5014.52 4246.88,5014.52 4284.44,4976.96 4355.04,4976.96 4652,4680 5037,4680 5057.54,4700.54 5144.79,4700.54 U32.9@5146.54,4702.28
Vbackup: C38_P.2 C79_P.1 C80_P.1 L15_P.1 Q4_P.2 R38_P.1 R39_P.1 R42_P.1 R43_P.2 R69_P.2 R70_P.2 | length 1372.2
  Top Layer w10: R70_P.2@4460,1420.5 v1(4497.5,1420.5) R69_P.2@4535,1420.5
  Top Layer w20: C38_P.2@4805.67,2414 4810,2409.67 4810,2282.7 4873.78,2218.92 5059.99,2218.92 v1(5140.5,2299.43)
  Layer 2 w10: v1(4497.5,1420.5) 4497.5,1686.5 v1(4500,1689)
  Bottom Layer w20: R42_P.1@4660,2295.5 4660,2319 4693.58,2352.58 4810,2352.58 ; C38_P.2@4805.67,2414 4810,2409.67 4810,2352.58 ; R43_P.2@4810,2295.5 4810,2352.58 ; R38_P.1@5041.5,2345.5 5041.5,2298.65 Q4_P.2@5047.4,2292.74 5054.09,2299.43 v1(5140.5,2299.43) 5143.06,2301.99 R39_P.1@5185,2301.99
  other v1: 4540,1689 4580,1689 4620,1689 4660,1689 4700,1689 4740,1689 4780,1689 4820,1689 4860,1689
VBIAS_1: R127.1 R131.2 U24.3 | length 180.4
  Top Layer w10: U24.3@4707.79,5660.8 4759.4,5660.8 4792.35,5693.76 R127.1@4827.59,5693.76 R131.2@4827.59,5646.79
VREF_500mV: R129.1 R133.2 U29.4 | length 144.5
  Top Layer w10: R133.2@5063.38,5670.26 5114.31,5670.26 5114.31,5717.71 5126.97,5730.37 U29.4@5126.97,5758.56
VREF_Input_Midsupply: R130.1 R134.2 U30.4 | length 116.2
  Top Layer w10: U30.4@5666.85,5686.37 5697,5686.37 5702.24,5681.13 R130.1@5742.56,5681.13 R134.2@5742.56,5642.79
VSENSE: R153.2 U26.4 U28.3 | length 314.2
  Top Layer w10: U28.3@5152.96,6026.89 5182.49,6026.89 5221.93,6066.34 5264.18,6066.34 5275.56,6054.96 R153.2@5275.56,6024.88 5275.56,5999.96 5335.75,5939.76 U26.4@5366.19,5939.76
pads on no net: FID1.1 FID2.1 FID3.1 H1.1 H2.1 H3.1 H4.1 H5.1 H6.1 J3.8 J3.10 J3.11 J3.12 J19. J20. J21. J22. J23. J24. J25. J26. LBL1.0 P1.2 P1.6 P1.10 P1.12 P1.13 P1.14 T1_P.1 U7_P.7 U7_P.12 U7_P.20 U7_P.25@3360.8,718.8 U7_P.25@3360.8,769.2 U7_P.25@3411.2,718.8 U7_P.25@3411.2,769.2 U10_P.3 U11_P.4 U12_P.10 U12_P.14 U12_P.17@4760,1389 U32.5 U32.6 U32.13 U32.14 U32.15 U32.16 U32.19 U32.20 U32.21 U32.22 U32.23 U32.24 U32.28 U32.29 U32.30 U32.31 U33.6 U33.7 U33.12 U33.13 U34.6 U34.7 U34.12 U34.13 U35.6

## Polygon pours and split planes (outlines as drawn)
PGND on Layer 1 "LAYER_1_PGND_P1410" (solid, pour order 1410): 3110,2639 5335,2639 5335,264 2835,264 2835,989 3210,1364 3210,1639 3110,1639
PGND on Layer 1 "Layer 1-PGND" (solid, pour order 1404): 4765,6782.96 6298.13,6782.96 6963.13,6117.96 6959.13,6113.96 6959.13,656.96 6602.13,299.96 4765,299.96
GND on Layer 1 "LAYER_1_GND_P1286" (solid, pour order 1286): 2410,2114 2410,2239 2411.73,2237.27 2730.84,2237.27 2855,2129 2855,1434 2535,1114 2535,389 2410,264 1460,264 1385,339 1385,714 1485,814 1485,964 1410,1039 1410,1814 1710,2114
N_OUT on Layer 1 "LAYER_1_N_OUT_P1425" (solid, pour order 1425): 1825,4667.26 3030,4667.26 3070,4627.26 3070,4327.26 3015,4272.26 1825,4272.26 1785,4312.26 1785,4627.26
LINE3_OUT on Layer 1 "LAYER_1_LINE3_OUT_P1423" (solid, pour order 1423): 1830,5197.26 3035,5197.26 3075,5157.26 3075,4857.26 3020,4802.26 1830,4802.26 1790,4842.26 1790,5157.26
LINE2_OUT on Layer 1 "LAYER_1_LINE2_OUT_P1421" (solid, pour order 1421): 1820,5725 3025,5725 3065,5685 3065,5385 3010,5330 1820,5330 1780,5370 1780,5685
LINE1_OUT on Layer 1 "LAYER_1_LINE1_OUT_P1419" (solid, pour order 1419): 1810,6260 3015,6260 3055,6220 3055,5920 3000,5865 1810,5865 1770,5905 1770,6220
N_IN on Layer 1 "LAYER_1_N_IN_P1417" (solid, pour order 1417): 275,4655 1480,4655 1520,4615 1520,4315 1465,4260 275,4260 235,4300 235,4615
LINE3_IN on Layer 1 "LAYER_1_LINE3_IN_P1415" (solid, pour order 1415): 270,5185 1475,5185 1515,5145 1515,4845 1460,4790 270,4790 230,4830 230,5145
LINE2_IN on Layer 1 "LAYER_1_LINE2_IN_P1413" (solid, pour order 1413): 285,5730 1490,5730 1530,5690 1530,5390 1475,5335 285,5335 245,5375 245,5690
LINE1_IN on Layer 1 "LAYER_1_LINE1_IN_P1411" (solid, pour order 1411): 285,6265 1490,6265 1530,6225 1530,5925 1475,5870 285,5870 245,5910 245,6225
PGND on Layer 1 "Layer 1-PGND 1" (solid, pour order 1408): 971,4014 977,4020 2291,4020 2291,3666 3122,2835 4848,2835 4848,2605 3138,2605 2792,2605 2562,2835 1616,2835 1564,2887 1564,3384 987,3384 947,3424 947,3981
PGND on Layer 1 "Layer 1-PGND 2" (solid, pour order 1288): 4100,6768 4108,6776 4831,6776 4831,4611 4077,4611 4077,6743 4102,6768
no net on Layer 1 "LAYER_1_NONET_P1284" (solid, pour order 1284): 1810,2589 2460,2589 2485,2564 2485,2364 2460,2339 2260,2339 2210,2289 2210,2214 2185,2189 1810,2189 1785,2214 1785,2564
PGND on Top Layer "TOP_LAYER_PGND_P1384" (solid, pour order 1384): 3110.49,2629 5335.49,2629 5335.49,254 2835.49,254 2835.49,979 3210.49,1354 3210.49,1629 3110.49,1629
NetD20_P_2 on Top Layer "TOP_LAYER_NETD20_P_2_P1310" (solid, pour order 1310): 3020,829 3030,839 3275,839 3285,829 3340,829 3340,809 3330,809 3320,799 3320,789 3140,789 3113.27,762.27 3113.27,619.67 3034.53,619.67 3025.2,629 3025,629 3020,634
GND on Top Layer "TOP_LAYER_GND_P1324" (solid, pour order 1324): 1835,2114 2160,2114 2210,2064 2210,1889 2235,1864 2835,1864 2860,1839 2860,1439 2710,1289 1860,1289 1835,1314
N_OUT on Top Layer "TOP_LAYER_N_OUT_P1366" (solid, pour order 1366): 1827.5,4665 3032.5,4665 3072.5,4625 3072.5,4325 3017.5,4270 1827.5,4270 1787.5,4310 1787.5,4625
LINE2_IN on Top Layer "TOP_LAYER_LINE2_IN_P1374" (solid, pour order 1374): 285,5730 1490,5730 1530,5690 1530,5390 1475,5335 285,5335 245,5375 245,5690
LINE1_IN on Top Layer "TOP_LAYER_LINE1_IN_P1378" (solid, pour order 1378): 285,6265 1490,6265 1530,6225 1530,5925 1475,5870 285,5870 245,5910 245,6225
LINE3_IN on Top Layer "TOP_LAYER_LINE3_IN_P1380" (solid, pour order 1380): 270,5185 1475,5185 1515,5145 1515,4845 1460,4790 270,4790 230,4830 230,5145
N_IN on Top Layer "TOP_LAYER_N_IN_P1382" (solid, pour order 1382): 275,4655 1480,4655 1520,4615 1520,4315 1465,4260 275,4260 235,4300 235,4615
LINE3_OUT on Top Layer "TOP_LAYER_LINE3_OUT_P1372" (solid, pour order 1372): 1832.5,5195 3037.5,5195 3077.5,5155 3077.5,4855 3022.5,4800 1832.5,4800 1792.5,4840 1792.5,5155
LINE1_OUT on Top Layer "TOP_LAYER_LINE1_OUT_P1370" (solid, pour order 1370): 1810,6260 3015,6260 3055,6220 3055,5920 3000,5865 1810,5865 1770,5905 1770,6220
LINE2_OUT on Top Layer "TOP_LAYER_LINE2_OUT_P1330" (solid, pour order 1330): 1820,5725 3025,5725 3065,5685 3065,5385 3010,5330 1820,5330 1780,5370 1780,5685
NetQ2_P_4 on Top Layer "TOP_LAYER_NETQ2_P_4_P1326" (solid, pour order 1326): 1810,2589 2460,2589 2485,2564 2485,2364 2460,2339 2260,2339 2210,2289 2210,2249 2190,2229 1815,2229 1785,2259 1785,2564
Vbackup on Top Layer "TOP_LAYER_VBACKUP_P1322" (solid, pour order 1322): 4885,1712.62 4885,1614 4435,1614 4435,1704 4443.62,1712.62
NetD32_P_2 on Top Layer "TOP_LAYER_NETD32_P_2_P1320" (solid, pour order 1320): 4675,1454 4675,1434 4690,1419 4715,1419 4715,1424 4725,1434 4755,1434 4755,1469 4800,1514 4990,1514 5000,1524 5000,1649 4900,1649 4900,1599 4725,1599 4715.35,1589 4715.35,1494.35
NetC83_P_1 on Top Layer "TOP_LAYER_NETC83_P_1_P1318" (solid, pour order 1318): 5055,1509 5035,1489 4850,1489 4845,1484 4845,1444 4865,1424 5110,1424 5115,1419 5115,1304 5100,1289 5084.99,1289 5080,1293.98 5080,1254 5230,1254 5275,1299 5275,1439 5210,1504 5210,1644 5195,1659 5075,1659 5055,1649
NetD22_P_1 on Top Layer "TOP_LAYER_NETD22_P_1_P1316" (solid, pour order 1316): 3450,719 3470,719 3494.98,694.02 3494.98,677.54 3486.39,668.96 3486.39,539.46 3530,495.85 3530,314 3500,284 3415,284 3416.5,285.5 3416.5,512.5 3405,524 3405,584 3415,594 3430,594 3445,609 3445,714
-14V_INV on Top Layer "TOP_LAYER_-14V_INV_P1314" (solid, pour order 1314): 3150,569 3265,569 3275,579 3275,584 3295,604 3345,604 3355,594 3355,524 3345,514 3265,514 3265,459 3260,454 3130,454 3130,549
NetC50_P_1 on Top Layer "TOP_LAYER_NETC50_P_1_P1312" (solid, pour order 1312): 3280,719 3320,719 3320,624 3315,619 3290,619 3255,584 3145,584 3120,559 3120,479 3110,469 2905,469 2840,534 2840,809 2860,829 3000,829 3000,614 3010,604 3130,604 3130,631.54 3137.46,639 3264.54,639 3265,639 3275,649 3275,714
+14V_INV on Top Layer "TOP_LAYER_+14V_INV_P1308" (solid, pour order 1308): 3045,1014 3065,1034 3280,1034 3295,1019 3295,869 3285,859 3045,859
PGND on Top Layer "TOP_LAYER_PGND_P1306" (solid, pour order 1306): 3010,439 3285,439 3286,440 3286,497 3386,497 3385,496 3385,289 3360,264 3035,264 3010,289
AGND2 on Top Layer "TOP_LAYER_AGND2_P1304" (solid, pour order 1304): 4640,1274 4755,1274 4755,1159 4640,1159
5V on Top Layer "TOP_LAYER_5V_P1302" (solid, pour order 1302): 4035,1264 4060,1289 4335,1289 4385,1239 4385,889 4360,864 4235,864 4235,1039 4210,1064 4085,1064 4035,1114
NetC66_P_1 on Top Layer "TOP_LAYER_NETC66_P_1_P1300" (solid, pour order 1300): 4035,714 4435,714 4485,664 4485,539 4335,389 4235,389 4235,564 4210,589 4060,589 4035,614
3V3 on Top Layer "TOP_LAYER_3V3_P1298" (solid, pour order 1298): 4510,639 4525,654 4595,654 4600,649 4600,499 4615,484 4775,484 4783.98,475.02 4788.54,475.02 4788.54,414 4570,414 4525,369 4440,369 4415,394 4415,444 4510,539 4510,549
NetC73_P_1 on Top Layer "TOP_LAYER_NETC73_P_1_P1296" (solid, pour order 1296): 4589,832 4592,835 4689,835 4698,844 4778.54,844 4798.54,864 5150,864 5175,839 5175,734 5155,714 4938.86,714 4868.86,784 4710,784 4695,799 4695,819 4691,823 4590.12,823
+12V on Top Layer "TOP_LAYER_+12V_P1294" (solid, pour order 1294): 4680,855 4579,855 4545,889 4545,974 4425,974 4405,954 4405,849 4455,799 4545,799 4575,829 4575,834 4584,843 4680,843
12V_In on Top Layer "TOP_LAYER_12V_IN_P1292" (solid, pour order 1292): 4410,1139 4485,1139 4485,1019 4410,1019
+12V on Top Layer "TOP_LAYER_+12V_P1290" (solid, pour order 1290): 5135.5,1216.72 5137.78,1219 5230,1219 5230,1074 5134.94,1074
PGND on Bottom Layer "BOTTOM_LAYER_PGND_P1400" (solid, pour order 1400): 3109.51,2629 5334.51,2629 5334.51,254 2834.51,254 2834.51,979 3209.51,1354 3209.51,1629 3109.51,1629
GND on Bottom Layer "BOTTOM_LAYER_GND_P1250" (solid, pour order 1250): 2235,1864 2235,1714 1835,1714 1835,2114 2160,2114 2210,2064 2210,1889
NetQ2_P_4 on Bottom Layer "BOTTOM_LAYER_NETQ2_P_4_P1218" (solid, pour order 1218): 1810,2589 2460,2589 2485,2564 2485,2364 2460,2339 2260,2339 2210,2289 2210,2214 2185,2189 1810,2189 1785,2214 1785,2564
LINE1_OUT on Bottom Layer "BOTTOM_LAYER_LINE1_OUT_P1398" (solid, pour order 1398): 1820,6260 3025,6260 3065,6220 3065,5920 3010,5865 1820,5865 1780,5905 1780,6220
LINE2_OUT on Bottom Layer "BOTTOM_LAYER_LINE2_OUT_P1396" (solid, pour order 1396): 1830,5725 3035,5725 3075,5685 3075,5385 3020,5330 1830,5330 1790,5370 1790,5685
LINE3_OUT on Bottom Layer "BOTTOM_LAYER_LINE3_OUT_P1394" (solid, pour order 1394): 1820,5190 3025,5190 3065,5150 3065,4850 3010,4795 1820,4795 1780,4835 1780,5150
N_OUT on Bottom Layer "BOTTOM_LAYER_N_OUT_P1392" (solid, pour order 1392): 1825,4665 3030,4665 3070,4625 3070,4325 3015,4270 1825,4270 1785,4310 1785,4625
N_IN on Bottom Layer "BOTTOM_LAYER_N_IN_P1390" (solid, pour order 1390): 275,4650 1480,4650 1520,4610 1520,4310 1465,4255 275,4255 235,4295 235,4610
LINE3_IN on Bottom Layer "BOTTOM_LAYER_LINE3_IN_P1388" (solid, pour order 1388): 285,5190 1490,5190 1530,5150 1530,4850 1475,4795 285,4795 245,4835 245,5150
LINE2_IN on Bottom Layer "BOTTOM_LAYER_LINE2_IN_P1386" (solid, pour order 1386): 265,5730 1470,5730 1510,5690 1510,5390 1455,5335 265,5335 225,5375 225,5690
LINE1_IN on Bottom Layer "BOTTOM_LAYER_LINE1_IN_P1256" (solid, pour order 1256): 275,6260 1480,6260 1520,6220 1520,5920 1465,5865 275,5865 235,5905 235,6220
NetD4_P_4 on Bottom Layer "BOTTOM_LAYER_NETD4_P_4_P1254" (solid, pour order 1254): 940,2369 1045,2369 1045,2259 940,2259
NetC6_P_1 on Bottom Layer "BOTTOM_LAYER_NETC6_P_1_P1252" (solid, pour order 1252): 1410,2014 1785,2014 1785,1414 1785,1214 1385,1214 1385,1989
NetQ1_P_5-6-7-8 on Bottom Layer "BOTTOM_LAYER_NETQ1_P_5-6-7-8_P1220" (solid, pour order 1220): 3706.67,2024 3721.67,2009 3740,2009 3755,1994 3755,1789 3750,1784 3510,1784 3490,1764 3490,1718.57 3475.43,1704 3400,1704 3375,1679 3375,1654 3350,1629 3235,1629 3175,1689 3175,2004 3195,2024
NetC21_P_1 on Bottom Layer "BOTTOM_LAYER_NETC21_P_1_P1248" (solid, pour order 1248): 3190,2039 3240,2039 3240,2009 3190,2009
NetC21_P_1 on Bottom Layer "BOTTOM_LAYER_NETC21_P_1_P1246" (solid, pour order 1246): 3191.25,1914 3240,1914 3240,1884 3191.25,1884
NetC21_P_1 on Bottom Layer "BOTTOM_LAYER_NETC21_P_1_P1244" (solid, pour order 1244): 3189.5,1788 3240,1788 3240,1758 3189.5,1758
NetC21_P_1 on Bottom Layer "BOTTOM_LAYER_NETC21_P_1_P1242" (solid, pour order 1242): 3888,1775 4083.05,1775 4083.58,1774.47 4083.58,1717.58 4005,1639 3889,1639 3888,1638
5V on Bottom Layer "BOTTOM_LAYER_5V_P1240" (solid, pour order 1240): 4235,1064 4385,1064 4385,869 4355,839 4235,839 4235,1039
NetC66_P_1 on Bottom Layer "BOTTOM_LAYER_NETC66_P_1_P1238" (solid, pour order 1238): 4235,589 4385,589 4385,439 4335,389 4235,389 4235,564
3V3 on Bottom Layer "BOTTOM_LAYER_3V3_P1236" (solid, pour order 1236): 4275,609 4265,619 4265,624 4265.51,624.51 4265.51,710.69 4283.82,729 4535,729 4600,664 4600,519 4585,504 4460,504 4410,554 4410,599 4400,609
NetC73_P_1 on Bottom Layer "BOTTOM_LAYER_NETC73_P_1_P1234" (solid, pour order 1234): 4822.01,864 5150,864 5175,839 5175,734 5155,714 4938.86,714 4868.86,784 4822.01,784
PGND on Bottom Layer "BOTTOM_LAYER_PGND_P1232" (solid, pour order 1232): 3085,2139 3160,2139 3160,1655.85 3151.85,1664 3085,1664
12V_In on Bottom Layer "BOTTOM_LAYER_12V_IN_P1230" (solid, pour order 1230): 3900,1937.21 4100,1937.21 4100,1855.79 4081.42,1837.21 3900,1837.21
NetC50_P_1 on Bottom Layer "BOTTOM_LAYER_NETC50_P_1_P1228" (solid, pour order 1228): 3505,389 3671.26,389 3685,375.26 3685,314 3635,264 3505,264
+12V on Bottom Layer "BOTTOM_LAYER_+12V_P1226" (solid, pour order 1226): 3645.5,821.72 3647.78,824 3795,824 3795,694 3645,694
5V on Bottom Layer "BOTTOM_LAYER_5V_P1224" (solid, pour order 1224): 3870,384 3718.74,384 3710,375.26 3710,314 3760,264 3870,264
GND on Bottom Layer "BOTTOM_LAYER_GND_P1222" (solid, pour order 1222): 2415,2224 2725,2224 2725,2089 2415,2089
